// Mitsubishi GX Works2 project: code_plc_misu_2chedo1hethong   PLC: FX1S

PROGRAM MAIN
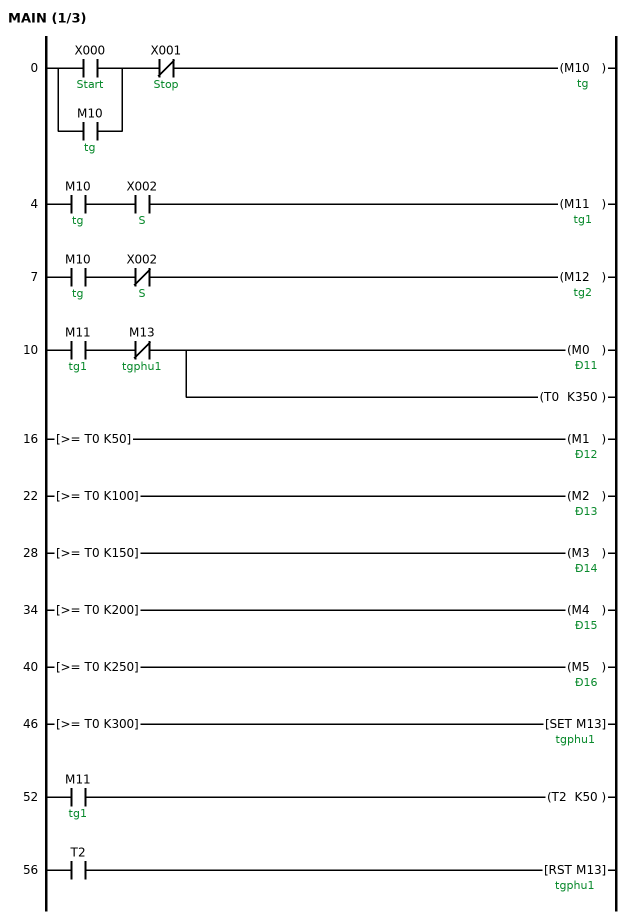
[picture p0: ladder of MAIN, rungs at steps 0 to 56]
0     LD      X000  ; Start
      OR      M10  ; tg
      ANI     X001  ; Stop
      OUT     M10  ; tg
4     LD      M10  ; tg
      AND     X002  ; S
      OUT     M11  ; tg1
7     LD      M10  ; tg
      ANI     X002  ; S
      OUT     M12  ; tg2
10    LD      M11  ; tg1
      ANI     M13  ; tgphu1
      OUT     M0  ; Đ11
      OUT     T0 K350
16    LD>=    T0 K50
      OUT     M1  ; Đ12
22    LD>=    T0 K100
      OUT     M2  ; Đ13
28    LD>=    T0 K150
      OUT     M3  ; Đ14
34    LD>=    T0 K200
      OUT     M4  ; Đ15
40    LD>=    T0 K250
      OUT     M5  ; Đ16
46    LD>=    T0 K300
      SET     M13  ; tgphu1
52    LD      M11  ; tg1
      OUT     T2 K50
56    LD      T2
      RST     M13  ; tgphu1
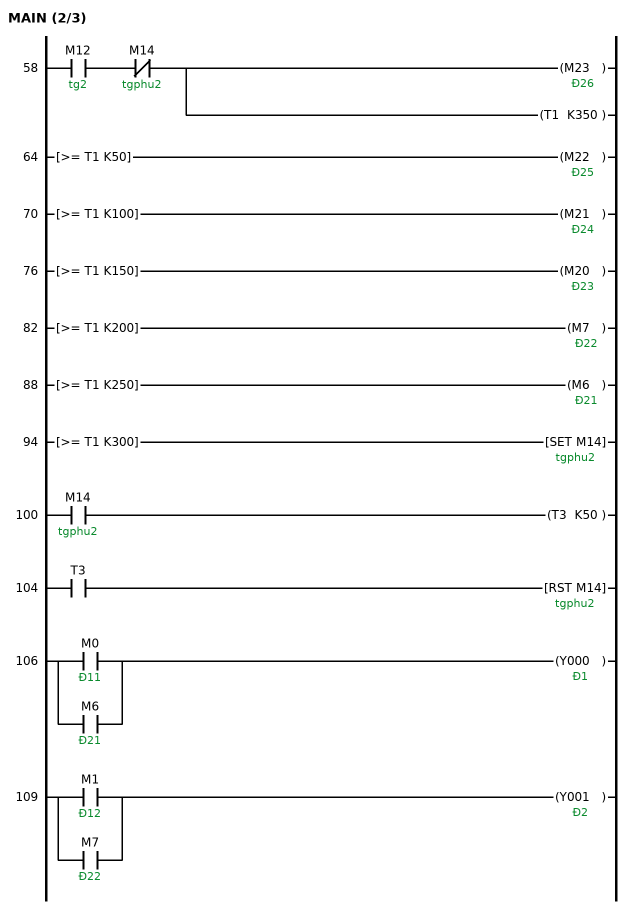
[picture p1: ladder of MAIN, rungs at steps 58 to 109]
58    LD      M12  ; tg2
      ANI     M14  ; tgphu2
      OUT     M23  ; Đ26
      OUT     T1 K350
64    LD>=    T1 K50
      OUT     M22  ; Đ25
70    LD>=    T1 K100
      OUT     M21  ; Đ24
76    LD>=    T1 K150
      OUT     M20  ; Đ23
82    LD>=    T1 K200
      OUT     M7  ; Đ22
88    LD>=    T1 K250
      OUT     M6  ; Đ21
94    LD>=    T1 K300
      SET     M14  ; tgphu2
100   LD      M14  ; tgphu2
      OUT     T3 K50
104   LD      T3
      RST     M14  ; tgphu2
106   LD      M0  ; Đ11
      OR      M6  ; Đ21
      OUT     Y000  ; Đ1
109   LD      M1  ; Đ12
      OR      M7  ; Đ22
      OUT     Y001  ; Đ2
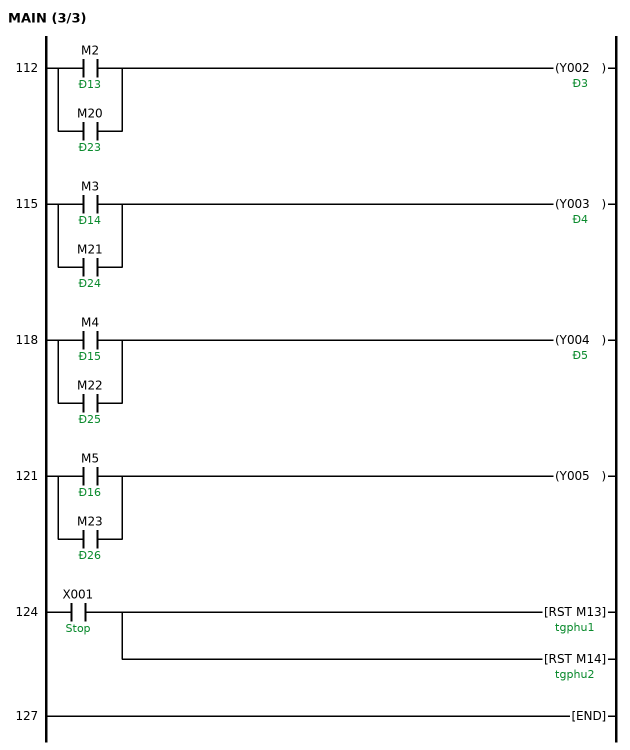
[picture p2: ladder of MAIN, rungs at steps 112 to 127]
112   LD      M2  ; Đ13
      OR      M20  ; Đ23
      OUT     Y002  ; Đ3
115   LD      M3  ; Đ14
      OR      M21  ; Đ24
      OUT     Y003  ; Đ4
118   LD      M4  ; Đ15
      OR      M22  ; Đ25
      OUT     Y004  ; Đ5
121   LD      M5  ; Đ16
      OR      M23  ; Đ26
      OUT     Y005
124   LD      X001  ; Stop
      RST     M13  ; tgphu1
      RST     M14  ; tgphu2
127   END
END_PROGRAM
